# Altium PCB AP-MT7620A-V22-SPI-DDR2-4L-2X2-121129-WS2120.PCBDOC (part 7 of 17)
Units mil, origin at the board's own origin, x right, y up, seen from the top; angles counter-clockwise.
Board outline 7316 x 4279 mil, 4 copper layers (Top, Inner Layer 2, Inner Layer 3, Bottom), stack 35.4 mil thick; 640 components, 473 nets, 2041 pads, 2358 vias.
Unrouted connection lines stored in the file: 11.
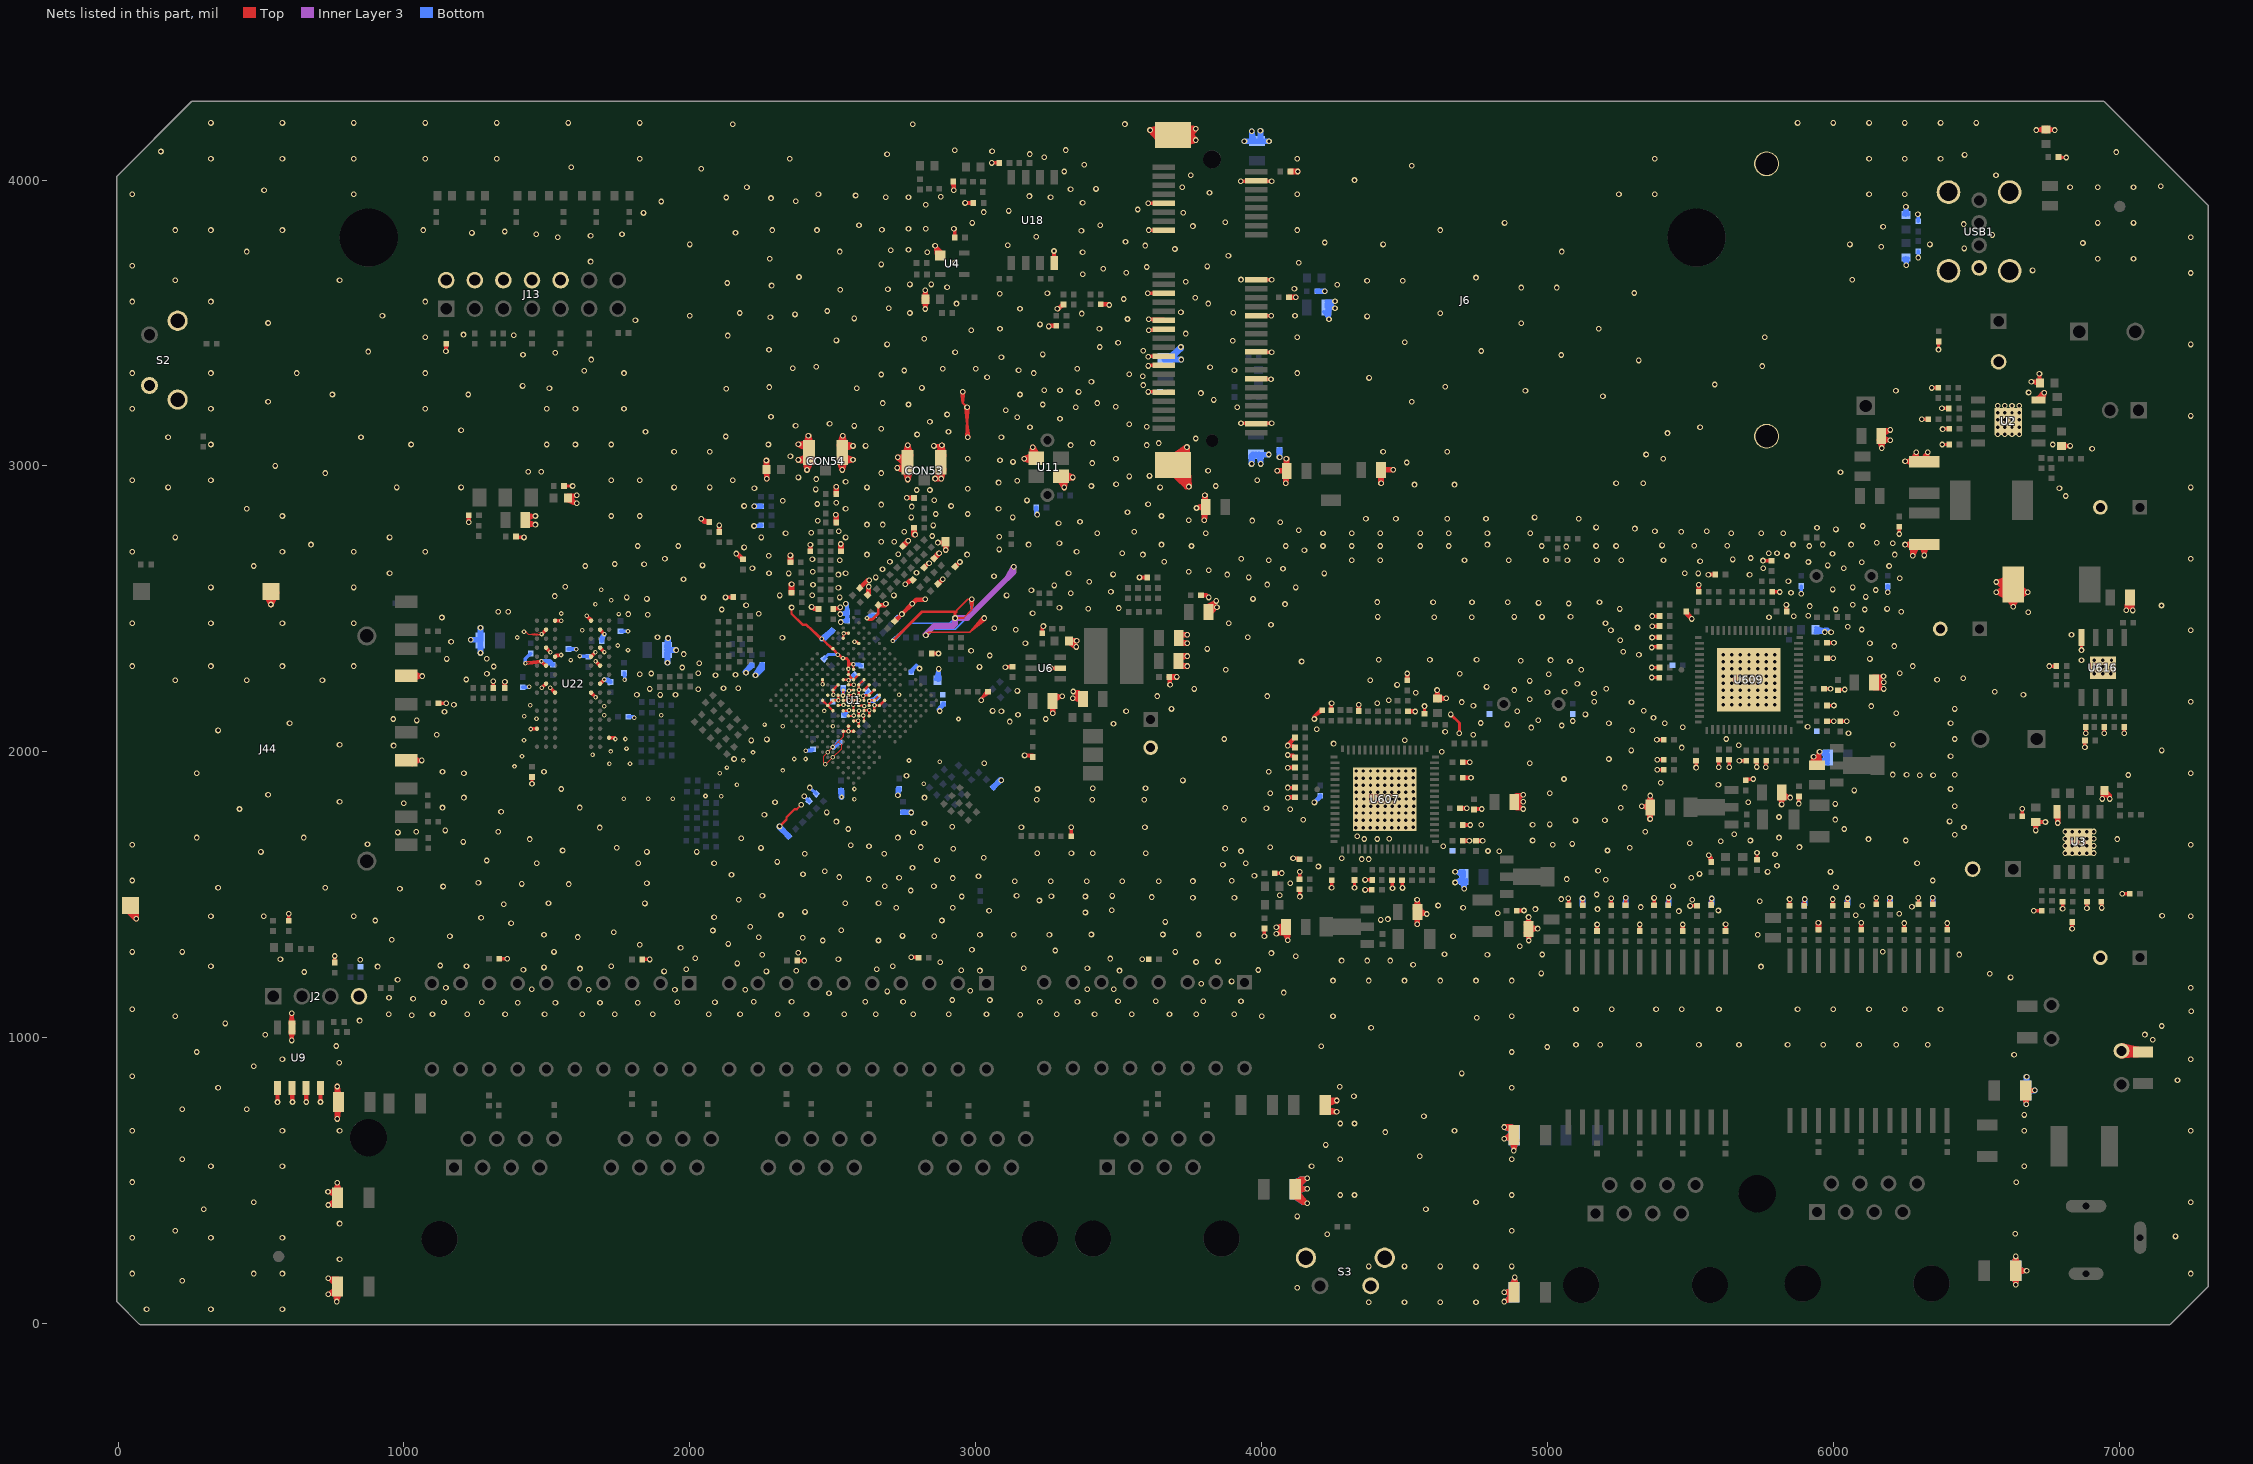
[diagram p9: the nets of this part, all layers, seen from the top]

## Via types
v1: diameter 20, hole 12, Top to Bottom, 2117 vias
v2: diameter 16, hole 8, Top to Bottom, 241 vias

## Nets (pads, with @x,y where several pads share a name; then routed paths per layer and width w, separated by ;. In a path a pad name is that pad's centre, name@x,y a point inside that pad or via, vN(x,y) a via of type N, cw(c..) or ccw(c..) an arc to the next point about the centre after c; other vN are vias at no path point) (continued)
GND: C1.2 C2.2 C5.2 C6.2 C7.2 C8.2 C9.2 C11.2 C12.2 C13.2 C16.2 C17.2 C18.2 C19.2 C21.2 C22.2 C23.2 C24.2 C29.2 C30.2 C32.2 C33.2 C34.2 C36.2 C39.2 C40.2 C41.2 C42.2 C43.2 C44.2 C45.2 C46.2 C47.2 C48.2 C50.2 C51.2 C52.2 C53.2 C54.2 C55.2 C56.2 C57.2 C58.2 C69.1 C70.2 C72.2 C73.2 C75.2 C76.2 C79.1 C82.2 C83.2 C87.2 C88.2 C90.2 C91.2 C93.2 C94.2 C97.2 C99.2 C100.2 C103.2 C104.2 C105.2 C107.2 C108.2 C110.2 C111.2 C112.2 C114.2 C115.2 C116.1 C117.1 C118.1 C119.1 C120.1 C121.2 C122.1 C125.2 C128.2 C129.2 C130.2 C131.2 C132.2 C133.2 C134.2 C135.2 C136.2 C137.2 C138.2 C139.2 C140.2 C166.2 C167.2 C193.2 C195.2 C200.2 C210.2 C215.2 C216.2 C217.2 C218.2 C219.2 C222.2 C223.2 C228.2 C229.2 C230.2 C231.2 C232.2 C275.2 C310.2 C311.2 C312.2 C313.2 C314.2 C315.2 C317.2 C318.2 C366.2 C455.1 C456.2 C457.2 C631.2 C632.2 C633.2 C634.2 C635.2 C636.2 C637.2 C638.2 C639.2 C640.2 C641.2 C642.2 C643.2 C644.2 C645.2 C646.2 C647.2 C648.2 C649.2 C650.2 C651.2 C652.2 C654.2 C655.2 C656.2 C657.2 C658.1 C660.2 C661.2 C662.2 C663.2 C664.2 C665.1 C667.2 C668.2 C669.2 C670.2 C671.2 C673.2 C674.2 C675.2 C676.2 C677.2 C678.2 C680.2 C681.2 C682.2 C683.2 C684.2 C686.2 C687.2 C688.2 C706.2 C707.2 C708.2 C709.2 C710.2 C711.2 C712.2 C713.2 C714.1 C715.1 C716.1 C717.1 C718.2 C719.2 C720.2 C721.2 C722.2 C723.2 C724.2 C725.2 C726.1 C727.1 C728.1 C729.1 C730.1 C731.1 C733.1 C734.1 C768.2 C769.2 C796.2 C797.2 C798.2 C799.2 C801.2 C802.2 C803.2 C804.2 C806.2 C807.2 C808.2 C809.2 C810.1 C811.2 C812.2 C813.2 C814.1 C815.2 C816.1 C817.1 C821.2 C840.2 C841.2 C842.2 C843.2 C844.2 C845.2 C846.2 C847.2 C848.2 C849.2 CON53.2 CON53.3 CON54.2 CON54.3 D3.1 D4.1 D42.1 J2.4 J6.4 J6.9 J6.15 J6.18 J6.21 J6.26 J6.27 J6.29 J6.34 J6.35 J6.37 J6.40 J6.43 J6.50 J6.53 J6.54 J6.57 J6.58 J13.2 J13.4 J13.6 J13.8 J13.10 J44.3 J44.6 J44.GND1 J44.GND2 L6.2 L9.2 L36.2 R5.2 R7.2 R11.2 R12.2 R19.2 R24.2 R42.1 R51.2 R54.2 R107.2 R126.1 R127.1 R130.1 R131.1 R134.1 R135.1 R139.1 R142.1 R159.1 R257.2 R271.2 R274.2 R351.2 R381.2 R467.2 R468.2 R477.1 R560.2 R561.2 R676.2 R678.2 R679.2 R680.2 R682.2 R691.2 R694.2 R698.2 R699.2 R718.2 R721.2 R723.2 R728.2 R743.2 R744.2 R813.2 R825.2 RC1.2 RC2.2 RC3.2 S2.2 S2.3 S2.4 S3.2 S3.3 S3.4 U1.C2 U1.C4 U1.D2 U1.F2 U1.F6 U1.F7 U1.F8 U1.F9 U1.F10 U1.F11 U1.F12 U1.G6 U1.G7 U1.G8 U1.G9 U1.G10 U1.G11 U1.G12 U1.H6 U1.H7 U1.H8 U1.H9 U1.H10 U1.H11 U1.H12 U1.J6 U1.J7 U1.J8 U1.J9 U1.J10 U1.J11 U1.J12 U1.K4 U1.K6 U1.K7 U1.K8 U1.K9 U1.K10 U1.K11 U1.K12 U1.L6 U1.L7 U1.L8 U1.L9 U1.L10 U1.L11 U1.L12 U1.M6 U1.M7 U1.M8 U1.M11 U1.M12 U1.N11 U2.4 U2.9 U3.4 U3.9 U4.1 U6.5 U9.1 U9.2 U9.3 U9.4 U9.7 U11.2 U11.4 U18.4 U22.A3 U22.A7 U22.B2 U22.B8 U22.D2 U22.D8 U22.E3 U22.E7 U22.F2 U22.F8 U22.H2 U22.H8 U22.J3 U22.J7 U22.N1 U22.P9 U607.65 U609.65 U616.4 U616.9 UC1.2 UC2.2 USB1.4 USB1.5 USB1.6 USB1.7 USB1.8 | length 52183.3
  Top w4: v2(1420,2420) 1427,2420 1435,2412 v2(1481.5,2412) ; v2@1424.48,2315.98 1471.14,2317 ; v2@1426.28,2304.14 1471.14,2317 ; v2@1479.31,2322.76 1435.16,2306.68 ; v2@1479.91,2322.9 1435.04,2311.52 ; v2@1480.51,2322.98 1435,2316.21 ; v2@1480.61,2311.01 1435,2317 v2@1480.61,2322.99 ; v2@1480.71,2311.01 1435,2316.21 ; v2@1481.11,2406.01 1435.5,2412 v2@1481.11,2417.99 ; v2@1481.32,2311.01 1435.04,2311.52 ; v2@1481.94,2311.07 1435.16,2306.68 ; U1.N11@2532.93,2071.01 2536.81,2053.31 ; U1.N11@2540.69,2071.01 2536.81,2053.31 ; 1435,2316.21 v2(1481,2317) ; 1435.04,2311.52 v2(1481,2317) ; 1435.16,2306.68 v2(1481,2317) ; 1471.14,2317 v2(1425,2310) 1432,2317 v2(1481,2317) ; 2519.25,2035.75 2536.81,2053.31 ; 2519.25,2035.75 2531,2024 2531,2011.5 v2(2500.5,1981) 2476,1956.5 v2(2473.5,1956.5) 2468,1962 2468,1984.5 v2(2482.5,1999) v2(2500.5,2017) 2519.25,2035.75 ; 2536.81,2053.31 U1.N11@2536.81,2071.43 2536.81,2053.31
  Top w5: v1(2826,2408) 2836,2418 2980,2418 v1(3030,2468) 2983.39,2421.39 ; v1@3024.4,2472.99 2983.39,2421.39 ; v1@3034.99,2462.4 2983.39,2421.39
  Top w6: v1(2928,2468) 2957.46,2468 2986,2496.54 ; 2932,2490 2934,2492 2934,2495.46 2972.54,2534 v1(2986,2534) ; v1@2979.03,2533.35 2986,2496.54 ; v1@2992.97,2533.35 2986,2496.54 ; 2986,2496.54 v1(2986,2534) ; 2986,2496.54 v1(2986,2534)
  Top w8: v1(2314,1739) 2337.95,1762.95 2337.95,1771 2366.5,1799.55 2374.55,1799.55 v1(2390,1815) ; v1(2356,2505) 2356,2483 2394,2445 2407,2445 2456.5,2395.5 v2@2462.5,2395.5 ; 2409.86,2442.14 v2(2462,2396) v2@2462.5,2395.5 ; U1.K4@2464.43,2252.38 v2(2464.5,2236) U1.K4@2464.5,2252.38 ; v2(2536,2197) 2536.81,2197.81 U1.J7@2536.81,2216.19 ; U1.N11@2536.81,2071.43 v2(2555.3,2071.9) ; U1.L9@2536.81,2143.81 2555.81,2143.81 v2(2557,2145) ; U1.N11@2537.28,2071.9 v2(2555.3,2071.9) ; U1.M11@2554.9,2089.52 v2(2555.3,2071.9) ; U1.M11@2555.3,2089.13 v2(2555.3,2071.9) ; v2(2556,2180) v2@2554.9,2178.9 ; v2(2557,2214) v2@2559.19,2216.19 ; v2(2572,2164) v2@2573,2163 ; U1.M12@2572.53,2071.9 v2(2555.3,2071.9) ; U1.M12@2573,2071.43 v2(2555.3,2071.9) ; v2(2574,2127) 2573,2126 v2@2573,2125.71 ; v2(2574,2199) v2@2573.1,2198.1 ; v2(2574,2235) v2@2573.29,2234.29 ; v2(2592,2144) v2@2591.1,2143.1 ; v2(2592,2217) v2@2591.55,2217.45 ; v2(2607,2127) v2@2609.19,2124.81 ; v2(2610,2160) v2@2608.1,2161.9 ; v2(2646,2163) 2645.38,2162.38 v2@2645.38,2161.9 ; v1@2949.02,3259.55 2955,3220 ; v1@2960.98,3259.55 2955,3220 ; v1@2964.01,3204.7 2970,3145 v1@2975.99,3204.7 ; v1@2966,3100.1 2970,3160.02 ; v1@2972,3096 2970,3099 v1(2970,3205) 2955,3220 ; v1(2972,3100) 2970,3160.02 ; v1@2977.98,3100.5 2970,3160.02 ; v1(3020,2180) v1@3020,2187 ; C54.2@3038.38,2213.83 v1@3020,2187 ; C54.2@3043,2210 v1@3020,2187 ; C54.2@3046.83,2205.38 v1@3020,2187 ; v2@2462.5,2395.5 2481.07,2376.93 2481.07,2376.59 ; U1.M6@2464.43,2180 U1.M7@2482.52,2161.9 ; U1.M6@2464.43,2180 U1.M7@2482.52,2161.9 ; U1.M6@2464.43,2180 U1.M7@2482.52,2161.9 ; U1.M6@2464.43,2180 U1.M7@2482.52,2161.9 ; 2481.07,2376.59 2498.66,2359 U1.F2@2500.62,2360.95 ; 2481.07,2376.59 U1.F2@2500.62,2360.95 ; U1.M7@2482.52,2161.9 U1.L7@2500.62,2180 ; U1.M7@2482.52,2161.9 U1.M8@2500.62,2143.81 ; U1.M7@2482.52,2161.9 U1.L7@2500.62,2180 ; U1.M7@2482.52,2161.9 U1.L7@2500.62,2180 ; U1.M7@2482.52,2161.9 U1.M8@2500.62,2143.81 ; U1.M7@2482.52,2161.9 U1.L7@2500.62,2180 ; U1.M7@2482.52,2161.9 U1.M8@2500.62,2143.81 ; U1.M7@2482.52,2161.9 U1.M8@2500.62,2143.81 ; U1.L7@2500.62,2180 v2(2520,2180) ; U1.K6@2500.62,2216.19 2502.4,2214.41 v2(2502.4,2199.7) U1.K6@2500.62,2216.19 ; U1.K6@2500.62,2216.19 U1.J6@2518.71,2234.29 ; U1.K6@2500.62,2216.19 U1.J6@2518.71,2234.29 ; U1.K6@2500.62,2216.19 U1.J6@2518.71,2234.29 ; U1.K6@2500.62,2216.19 U1.J6@2518.71,2234.29 ; U1.F2@2500.62,2360.95 2499.73,2360.06 2518.89,2340.89 U1.F2@2500.62,2360.95 ; v2(2520,2180) 2520,2196.81 U1.K7@2518.71,2198.1 v2(2520,2180) ; v2@2537.65,2414.19 2537.65,2397.14 U1.D2@2536.81,2397.14 v2@2537.65,2414.19 ; v2@2537.65,2414.19 v2(2538.48,2414.19) v2@2538.48,2414.72 ; v2@2538.48,2414.72 2554.9,2414.72 U1.C2@2554.9,2415.24 v2@2538.48,2414.72 ; v2@2553.81,2180 v2@2554.9,2178.9 ; v2@2553.81,2180 U1.K8@2536.81,2180 v2@2553.81,2180 ; v2@2554.02,2252.38 U1.H6@2536.81,2252.38 v2@2554.02,2252.38 ; v2@2554.02,2252.38 v2(2555.5,2250.9) 2564.99,2260.39 ; v2@2554.9,2178.9 U1.K9@2554.9,2161.9 v2@2554.9,2178.9 ; U1.G6@2554.9,2270.48 2554.9,2289.9 U1.G6@2554.9,2270.48 ; U1.G6@2554.9,2270.48 2564.99,2260.39 ; U1.G6@2554.9,2270.48 2564.99,2260.39 ; v2@2559.19,2216.19 U1.H8@2573,2216.19 v2@2559.19,2216.19 ; 2564.99,2260.39 U1.G7@2573,2252.38 ; v2@2573,2125.71 U1.L10@2554.9,2125.71 v2@2573,2125.71 ; v2@2573,2163 U1.K10@2573,2143.81 v2@2573,2163 ; U1.G7@2573,2252.38 U1.F7@2591.1,2270.48 U1.G7@2573,2252.38 ; v2@2573.1,2198.1 U1.J8@2554.9,2198.1 v2@2573.1,2198.1 ; v2@2573.29,2234.29 U1.H7@2554.9,2234.29 v2@2573.29,2234.29 ; 2584.64,2385.5 U1.C4@2591.1,2379.05 ; 2584.64,2385.5 v2(2576.1,2385.5) U1.C4@2591.1,2379.05 ; 2584.64,2385.5 U1.C4@2591.1,2379.05 ; 2584.64,2385.5 U1.C4@2591.1,2379.05 ; v2(2589,2109) v2@2591.1,2106.9 ; v2(2589,2109) 2574.38,2109 U1.L11@2573,2107.62 v2(2589,2109) ; v2@2591.1,2106.9 U1.L12@2591.1,2089.52 v2@2591.1,2106.9 ; v2@2591.1,2143.1 U1.K11@2591.1,2125.71 v2@2591.1,2143.1 ; v2@2591.1,2217 U1.H9@2591.1,2198.1 v2@2591.1,2217 ; v2@2591.1,2217 v2@2591.55,2217.45 ; v2@2591.1,2217.9 U1.G8@2591.1,2234.29 ; v2@2591.1,2217.9 v2@2591.55,2217.45 ; v2@2591.1,2217.9 U1.G8@2591.1,2234.29 ; U1.G8@2591.1,2234.29 U1.F8@2609.19,2252.38 ; U1.G8@2591.1,2234.29 U1.F8@2609.19,2252.38 ; U1.G8@2591.1,2234.29 U1.F8@2609.19,2252.38 ; U1.G8@2591.1,2234.29 U1.F8@2609.19,2252.38 ; v2@2608.1,2161.9 U1.J10@2591.1,2161.9 v2@2608.1,2161.9 ; v2@2609.1,2198.1 U1.G10@2627.29,2198.1 ; v2@2609.1,2198.1 v2(2607,2196) v2@2609.19,2193.81 ; v2@2609.1,2198.1 U1.G10@2627.29,2198.1 ; v2@2609.19,2124.81 U1.K12@2609.19,2107.62 v2@2609.19,2124.81 ; v2@2609.19,2193.81 U1.H10@2609.19,2180 v2@2609.19,2193.81 ; v2@2627.29,2144.29 U1.J12@2627.29,2125.71 v2@2627.29,2144.29 ; v2@2627.29,2144.29 v2(2628,2145) ; v2@2627.29,2177.29 U1.H11@2627.29,2161.9 v2@2627.29,2177.29 ; v2@2627.29,2177.29 v2(2628,2178) 2630,2180 U1.G11@2645.38,2180 ; U1.G10@2627.29,2198.1 U1.F10@2645.38,2216.19 ; U1.G10@2627.29,2198.1 U1.F10@2645.38,2216.19 ; U1.G10@2627.29,2198.1 U1.F10@2645.38,2216.19 ; U1.G10@2627.29,2198.1 U1.F10@2645.38,2216.19 ; v2(2628,2145) 2610.38,2145 U1.J11@2609.19,2143.81 v2(2628,2145) ; v2@2645.38,2161.9 U1.G12@2663.48,2161.9 ; v2@2645.38,2161.9 U1.G12@2662,2161.9 ; v2@2645.38,2161.9 U1.H12@2645.38,2143.81 v2@2645.38,2161.9 ; v2@2645.38,2161.9 U1.G12@2663.48,2161.9 ; v2@2645.38,2161.9 U1.G12@2663.48,2161.9 ; U1.G11@2645.38,2180 U1.F11@2663.48,2198.1 U1.G11@2645.38,2180 ; U1.G12@2662,2161.9 U1.F12@2680.1,2180 ; U1.G12@2662,2161.9 U1.F12@2681.57,2180 ; U1.G12@2663.48,2161.9 U1.F12@2680.1,2180 ; U1.G12@2663.48,2161.9 U1.F12@2681.57,2180 ; U1.F12@2680.1,2180 U1.F12@2681.57,2180 ; 2955,3220 v1(2955,3260) 2955,3220 ; U1.L8@2518.71,2161.9 2520.81,2164 v2(2537.6,2164) U1.L8@2518.71,2161.9 ; U1.J9@2573,2180 2574,2181 v2(2592,2181) U1.J9@2573,2180 ; U1.F6@2573,2288.57 2573,2306 U1.F6@2573,2288.57 ; U1.G9@2609.19,2216.19 U1.F9@2627.29,2234.29 U1.G9@2609.19,2216.19
  Top w10: U1.K4@2464.43,2252.38 U1.K4@2464.5,2252.38 ; v2(2518,2340) 2518.89,2340.89 2519.5,2341.5 2534.5,2326.5 v2(2536,2328) 2536,2326 2549,2326 2555,2320 2555,2307 ; v2@2554.9,2289.9 v2(2555,2290) 2555,2307 ; v2@2573,2306 v2(2572.5,2306.5) 2572,2307 2555,2307 ; v2@2622,2468 v2(2620,2468) 2625,2463 2637.97,2463 2659.39,2484.42 ; v2(2710,2388) 2812,2490 2932,2490 2928,2486 v1(2928,2468) ; v1(4662,2131) 4692,2101 v1(4692,2065) ; C842.2@2659.22,2513.12 2659.39,2493.98 ; C842.2@2659.22,2513.12 2659.39,2493.98 ; C842.2@2659.22,2513.12 2659.39,2484.42 ; 2659.39,2484.42 2659.39,2493.98
  Top w12: U9.7@602.02,1022.68 v1(607.9,990.5) ; U9.7@607.9,1013.8 v1(608.2,1085.8) ; U9.7@608,1023.21 v1(607.9,990.5) ; U9.7@613.98,1022.64 v1(607.9,990.5) ; R54.2@758,1263 v1(758,1286) ; C122.1@760.41,134.28 v1(735,159) ; C122.1@760.99,126.07 v1(735,103) ; C116.1@761.61,436.42 v1(735,415) ; C116.1@762.88,443.01 v1(734.5,461.5) ; C116.1@767.43,469.43 v1(734.5,461.5) ; C122.1@767.88,114.25 v1(735,103) ; C122.1@767.88,145.75 v1(735,159) ; C116.1@767.88,424.25 v1(735,415) ; C116.1@767.88,455.75 v1(734.5,461.5) ; C116.1@768.87,410.6 v1(735,415) ; C122.1@769.68,100.69 v1(735,103) ; C122.1@770.45,159.19 v1(735,159) ; J44.6@1028.96,2250.24 v1@1063.45,2265.55 ; J44.6@1028.96,2280.86 v1@1063.45,2265.55 ; J44.3@1029.4,1955.06 v1@1059,1970.28 ; J44.3@1029.4,1985.49 v1@1059,1970.28 ; C275.2@1121,2170 v1(1148.5,2170) ; C125.2@1313,2223 v1(1313,2247) ; C115.2@1334,1276 v1(1362,1276) ; C45.2@1424.45,2800 v1(1460,2795) ; C45.2@1424.45,2822 v1(1460,2825) ; C45.2@1424.6,2789 v1(1460,2795) ; C45.2@1425.22,2832.97 v1(1460,2825) ; C45.2@1427.05,2811.31 v1(1460,2825) ; C45.2@1427.63,2810.53 v1(1460,2795) ; v2(1444,2080) v2@1444.84,2080.84 ; v2(1550,2458.5) v2@1549.71,2458.79 ; C52.2@1560,2930 v1(1590,2930) ; C53.2@1571.66,2878.56 v1(1604.8,2869.8) ; C53.2@1573.56,2897.93 v1(1605,2898) ; C53.2@1574.59,2890 v1(1605,2898) ; C53.2@1577.59,2882.58 v1(1605,2898) ; C53.2@1579.17,2892.56 v1(1604.8,2869.8) ; U22.B8@1686.04,2427.3 v2(1701.5,2412) ; U22.P9@1717.54,2049.34 1735.66,2049.34 v2(1740,2045) ; C114.2@1834,1274 v1(1860,1274) ; C112.2@2376,1270 v1(2400,1270) ; U1.N11@2536.81,2071.43 U1.N11@2537.28,2071.9 ; U1.M11@2554.9,2089.52 U1.M11@2555.3,2089.13 ; U1.M12@2572.53,2071.9 U1.M12@2573,2071.43 ; RC1.2@2816.46,3580.1 v1(2824,3549) ; RC1.2@2816.47,3585.96 v1(2824,3615) ; RC1.2@2824.41,3581 v1(2824,3549) ; RC1.2@2824.41,3585 v1(2824,3615) ; RC1.2@2832.32,3586.17 v1(2824,3615) ; RC1.2@2832.33,3579.9 v1(2824,3549) ; U4.1@2863.51,3733.45 v1(2858,3770) ; U4.1@2874.5,3736.92 v1(2858,3770) ; U4.1@2875.68,3736.92 2875.68,3749.68 2877,3751 v1(2858,3770) ; U4.1@2883.88,3743.61 v1(2858,3770) ; v1(2924,3830) 2927,3827 C200.2@2927,3799 ; v1(3104,2296) v1@3106,2298 ; C29.2@3233,2415 3233,2436 v1(3237,2440) ; C48.2@3268.45,2178 3268.45,2190.45 3272,2194 v1(3303,2194) ; C48.2@3268.45,2189 v1(3303,2194) ; C48.2@3268.61,2200 v1(3303,2194) ; C48.2@3271.72,2178.5 v1(3303,2194) ; U6.5@3286.34,2293 v1(3263,2293) U6.5@3296.18,2293 ; C79.1@3334,1705 v1(3334,1736) ; C56.2@3369.74,2186.66 v1(3341,2211) ; C56.2@3373.24,2174.24 v1(3340,2187) ; C56.2@3374.47,2195.95 v1(3340,2187) ; C56.2@3375.55,2196 v1(3341,2211) ; C56.2@3378.41,2206.62 v1(3341,2211) ; J6.43@3628.47,3257.6 v1(3604,3259) 3656.6,3259 J6.43@3658,3257.6 ; J6.37@3628.47,3352.09 v1@3606.09,3352.09 ; J6.35@3628.47,3383.58 v1@3605.58,3383.58 ; J6.29@3628.47,3478.07 v1(3605,3475) 3654.93,3475 J6.29@3658,3478.07 ; J6.27@3628.47,3509.57 v1(3605,3513) 3658,3513 J6.27@3658,3509.57 ; J6.21@3628.47,3604.06 v1(3602,3604) 3657.94,3604 J6.21@3658,3604.06 ; J6.15@3628.47,3824.53 v1(3605,3825) 3657.53,3825 J6.15@3658,3824.53 ; J6.9@3628.47,3919.02 v1(3604,3919) J6.9@3658,3919.02 ; C46.2@3807.9,2509.84 v1@3841.86,2528.14 ; C46.2@3814.64,2512 v1(3844,2506) ; C46.2@3818.24,2490.68 v1(3844,2506) ; C46.2@3823.22,2494.37 v1@3841.86,2528.14 ; v1(3842,2528) v1@3841.86,2528.14 ; J6.50@3951.31,3147.36 v1(3928,3149) 3979.19,3149 J6.50@3980.83,3147.36 3982.47,3149 v1(4035,3149) J6.50@4010.36,3147.36 ; J6.4@3951.31,3997.76 v1(3927,3996) J6.4@3985,3996 ; J6.40@3980.83,3304.84 3982.68,3303 v1(4033,3303) J6.40@4010.36,3304.84 ; J6.34@3980.83,3399.33 3982.17,3398 v1(4035,3398) J6.34@4010.36,3399.33 ; J6.26@3980.83,3525.32 3981.15,3525 v1(4034,3525) J6.26@4010.36,3525.32 ; J6.18@3980.83,3651.3 3981.13,3651 v1(4035,3651) J6.18@4010.36,3651.3 ; J6.4@3980.83,3997.76 3982.59,3996 J6.4@3985,3996 ; v1(4010,1355) R468.2@4010,1382 ; J6.4@4010.36,3997.76 v1(4035,3996) J6.4@3985,3996 ; v1(4051.99,1386.05) v1@4053.99,1388.05 ; C631.2@4080.05,1386.58 v1(4051.99,1364.05) ; C631.2@4083.62,1377.22 v1@4053.99,1388.05 ; C631.2@4083.62,1398.88 v1@4053.99,1388.05 ; C631.2@4085.54,1377.05 v1(4051.99,1364.05) ; C631.2@4085.54,1388.05 v1@4053.99,1388.05 ; C631.2@4087.9,1366.31 v1(4051.99,1364.05) ; C631.2@4091.8,1364.05 v1(4051.99,1364.05) ; C117.1@4113.51,498.63 v1(4160,508) ; C117.1@4126.22,474.72 v1(4160,508) ; v1(4185,2115) 4185,2125 ; C642.2@4244,2145 4244,2169 v1(4245,2170) ; v1(4325,1525) C647.2@4325,1552 ; v1(4362,1517) v1@4363,1518 ; R718.2@4570,2133 v1(4570,2160) ; RC2.2@4607.12,2187.96 v1@4615,2210 ; v1(4614,2216) v1@4615,2210 ; RC2.2@4617,2186.59 v1(4646,2187) ; RC2.2@4617.99,2194.53 v1(4646,2187) ; RC2.2@4618.22,2178.68 v1(4646,2187) ; RC2.2@4622.88,2187.96 v1@4615,2210 ; C734.1@4869.39,641.94 v1(4882.6,605.4) ; C733.1@4869.65,129.25 v1(4885.3,161.6) ; C733.1@4874.58,105.13 v1(4849,77) ; C734.1@4875.53,671.54 v1(4848.8,646.4) ; C733.1@4880.12,96.6 v1(4849,110) ; C733.1@4880.12,123.4 v1(4849,110) ; C680.2@4880.35,1845.61 v1(4915,1850) ; C680.2@4880.93,1802.34 v1(4915,1800) ; C733.1@4882.88,94.25 v1(4849,77) ; C733.1@4882.88,125.75 v1(4885.3,161.6) ; C734.1@4882.88,644.25 v1(4882.6,605.4) ; C680.2@4883.44,1813.05 v1(4915,1800) ; C680.2@4883.44,1835.05 v1(4915,1850) ; C734.1@4885.49,646.57 v1(4848.8,646.4) ; C733.1@4886.8,81.14 v1(4849,77) ; C680.2@4889.22,1822.41 v1(4915,1800) ; C680.2@4889.65,1825.97 v1(4915,1850) ; C734.1@4896.34,641.74 v1(4882.6,605.4) ; C733.1@4896.46,127.44 v1(4885.3,161.6) ; C682.2@4922.71,1394.47 v1@4933.44,1417 ; C682.2@4922.74,1367.48 v1(4935,1340) ; C682.2@4933.44,1370.05 v1(4935,1340) ; C682.2@4933.44,1392.05 v1@4933.44,1417 ; C682.2@4944.17,1394.47 v1@4933.44,1417 ; C682.2@4944.34,1368.6 v1(4935,1340) ; v1(5073,1488) 5074,1487 C706.2@5074,1463 ; C637.2@5348.73,1819.06 v1(5359.5,1847) ; C637.2@5356.1,1795.6 v1(5330,1810) ; C637.2@5358.96,1817.03 v1(5330,1810) ; C637.2@5359.54,1804.99 C637.2@5359.54,1806.05 ; C637.2@5359.54,1817.05 v1(5359.5,1847) ; v1(5365,2365) 5368.05,2368.05 C645.2@5391.99,2368.05 ; v1(5366,2400) 5367,2401 R694.2@5391,2401 ; v1(5367,2439) 5368,2440 R698.2@5392,2440 ; v1(5367,2475) R699.2@5392,2475 ; C637.2@5370.35,1819.08 v1(5359.5,1847) ; v1(5373,1489) v1(5373,1489) C710.2@5373.05,1463 ; C711.2@5423.05,1463 5423.05,1488.05 v1(5424,1489) ; v1(5499,1461) v1@5500,1462 ; C713.2@5573,1464 5573,1487 v1(5575,1487) ; C660.2@5694,1900 5694,1905 v1(5720,1905) C660.2@5694,1901 ; R561.2@5733,1623 v1(5733,1647) ; C664.2@5785.99,2560.05 5811.95,2560.05 v1(5813,2559) ; C671.2@5808.6,1844.19 v1(5819,1816) ; C671.2@5819.23,1835.05 v1(5849,1840) ; C671.2@5823.57,1856.24 v1(5849,1840) ; C671.2@5830.22,1843.88 v1(5819,1816) ; C718.2@5847,1462 v1(5847,1485) ; C719.2@5898,1462 5898,1483 v1(5900,1485) ; C687.2@5921.13,1955.13 v1(5931,1983) ; C687.2@5932,1953.45 v1(5931,1983) ; C687.2@5942.73,1955.86 v1(5931,1983) ; C687.2@5943,1953.45 5940.82,1955.62 5938.45,1958 5931,1958 v1(5931,1983) ; C676.2@5967,2221 v1(5990,2221) ; C720.2@5998,1462 v1(5998,1485) ; C681.2@6023.99,2107.05 v1(6046.99,2107.05) ; C721.2@6048,1464 6048,1484.9 v1(6050.1,1487) ; C686.2@6140.39,2263.86 v1@6176,2265 ; C686.2@6140.52,2263.88 v1(6175.5,2264.5) ; C686.2@6140.67,2220.19 v1(6176,2220) ; C686.2@6142.44,2231.05 v1(6176,2220) ; C686.2@6143.93,2252.95 v1(6176,2243) ; C686.2@6144.55,2231.25 v1(6176,2243) ; C686.2@6147.46,2240.84 v1(6176,2220) ; C686.2@6147.63,2243.35 v1(6175.5,2264.5) ; C686.2@6147.68,2243.38 v1@6176,2265 ; C722.2@6150,1467 v1(6150,1490) ; C219.2@6165.91,3126.89 v1(6199,3126) ; C219.2@6167.45,3094 v1(6199,3090) ; C219.2@6167.45,3116 v1(6199,3126) ; C219.2@6167.97,3083.01 v1(6199,3090) ; C219.2@6170.7,3104.51 v1(6199,3090) ; C219.2@6172.47,3106.21 v1(6199,3126) ; C723.2@6198,1466 v1(6198,1490) ; v1(6231,2762) C840.2@6231,2787 ; C311.2@6271.78,3020.08 v1(6290,3048) ; C310.2@6278.2,2725 v1(6251,2725) ; v1(6297,1490) 6298,1489 C724.2@6298,1467 ; C311.2@6298.21,3015.69 v1(6290,3048) ; C310.2@6304.54,2722.41 v1(6318,2687) ; C311.2@6306.31,3022.23 v1(6330,3048) ; C310.2@6331.46,2722.41 v1(6318,2687) ; C311.2@6331.52,3013.03 v1(6330,3048) ; v1(6344,3273) v1@6345,3274 ; C725.2@6348,1467 v1(6348,1490) ; v1(6382,3129) v1@6383,3130 ; C730.1@6398,1378 v1(6398,1401) ; C816.1@6624.72,166.48 v1(6638,136) ; C816.1@6624.7,203.44 v1(6638,235) ; D42.1@6628.94,2585 6629,2584.94 D42.1@6629,2569 ; D42.1@6636.72,2559.62 v1(6629,2508) ; C816.1@6638.12,169.25 v1(6638,136) ; C816.1@6638.12,200.75 v1(6638,235) ; C816.1@6640.59,171.54 v1(6676,185) ; C816.1@6640.59,198.46 v1(6676,185) ; D42.1@6648.38,2556.46 v1(6629,2508) ; C816.1@6651.5,166.39 v1(6638,136) ; C816.1@6651.52,203.53 v1(6638,235) ; D42.1@6659.24,2550.55 v1(6629,2508) ; C731.1@6659.94,795.58 v1(6675,767) ; C17.2@6661,1775 v1(6661,1801) ; C731.1@6673.12,799.25 v1(6675,767) ; C731.1@6676.36,801.7 v1@6702,815 ; C731.1@6676.36,828.3 v1@6702,815 ; C731.1@6686.64,797.14 v1(6675,767) ; C23.2@6700.07,1753.32 v1(6708,1725) ; v1(6705,816) v1@6702,815 ; C23.2@6715.93,1753.32 v1(6708,1725) ; C13.2@6720.53,3284.22 v1(6693,3295) ; C13.2@6721.2,3291.2 C13.2@6717.41,3295 ; C13.2@6722.14,3300 v1(6693,3295) ; C13.2@6722.41,3290 C13.2@6717.41,3295 ; C13.2@6722.41,3292 v1(6693,3295) ; C366.2@6744,4177.59 6741.41,4175 v1(6710,4175) ; C366.2@6746,4177.59 v1(6775,4175) ; C366.2@6746.39,4169.6 v1(6775,4175) ; C366.2@6747.8,4185.39 v1(6775,4175) ; C8.2@6798,3069.41 6798.59,3070 v1(6828,3070) ; C8.2@6800,3069.41 v1(6828,3070) ; C8.2@6800.98,3077.35 v1(6828,3070) ; C8.2@6801.31,3061.52 v1(6828,3070) ; U616.4@6868,2379.84 v1(6868,2356) U616.4@6868,2399.33 ; C18.2@6940.67,1864.13 v1(6940.6,1835.2) ; C18.2@6948.59,1863 v1(6940.6,1835.2) ; C18.2@6948.59,1865 6940.6,1864.59 v1(6940.6,1835.2) ; C18.2@6955.9,1859.75 v1(6940.6,1835.2) ; L36.2@7005.53,932.7 R257.2@7064.62,936.69 ; L36.2@7005.95,944.78 R257.2@7064.62,936.69 ; L36.2@7007.2,963.52 R257.2@7066.54,963.78 ; L36.2@7008.13,944.56 R257.2@7067.25,950.12 ; L36.2@7008.38,975.55 R257.2@7066.54,963.78 ; L36.2@7008.71,944.58 R257.2@7071.5,954.06 ; L36.2@7008.71,963.53 R257.2@7071.5,954.06 ; L36.2@7009.39,963.45 R257.2@7067.25,950.12 ; L36.2@7010.3,944.84 R257.2@7066.54,963.78 ; L36.2@7010.48,932.7 R257.2@7067.25,950.12 ; L36.2@7011.51,962.88 R257.2@7064.62,936.69 ; L36.2@7011.64,932.87 R257.2@7071.5,954.06 ; L36.2@7011.64,975.24 R257.2@7071.5,954.06 ; L36.2@7013.29,974.9 R257.2@7067.25,950.12 ; L36.2@7015.31,933.84 R257.2@7066.54,963.78 ; L36.2@7017.93,973.12 R257.2@7064.62,936.69 ; C314.2@7026.7,2531.35 v1(7024.4,2495) ; C314.2@7027.43,2524.46 v1(7047,2494.6) ; C314.2@7037.45,2540 7036,2538.55 C314.2@7036,2535.8 ; C314.2@7047.01,2523.55 v1(7024.4,2495) ; C314.2@7048.37,2530.27 v1(7047,2494.6) ; R257.2@7083,950.12 7079.06,954.06 L36.2@7008,954.06 ; v1(607.9,990.5) v1@607.9,1085.5 ; v1@607.9,1085.5 v1(608.2,1085.8) ; v1@607.9,1085.5 602.01,1048.28 v1(608.2,1085.8) ; v1@607.9,1085.5 613.99,1048.31 v1(608.2,1085.8) ; v1@607.9,1085.5 608,1047.82 v1(608.2,1085.8) ; v1(734.5,461.5) 759.5,461.5 767.88,453.12 C116.1@767.88,440 760,440 757.5,437.5 757.5,415 v1(735,415) ; v1(735,103) 761,103 761,123.12 C122.1@767.88,130 767.88,137 767.88,145.12 754,159 v1(735,159) ; v1@1059,1970.28 v1(1062.5,1970) ; v1@1059,1970.28 J44.3@1008,1970.28 v1(1062.5,1970) ; v1@1059,1970.28 1025.72,1970.28 v1(1062.5,1970) ; v1@1063.45,2265.55 v1(1064,2265) ; v1@1063.45,2265.55 J44.6@1008,2265.55 v1(1064,2265) ; v1@1063.45,2265.55 1025.72,2265.55 v1(1064,2265) ; v2@1444.84,2080.84 U22.N1@1465.57,2080.84 v2@1444.84,2080.84 ; v1(1460,2795) 1424.45,2795 C45.2@1424.45,2811 1438.45,2825 v1(1460,2825) ; v2@1549.71,2458.79 U22.A3@1528.56,2458.79 v2@1549.71,2458.79 ; C53.2@1574.59,2886 v1(1604.8,2869.8) ; C53.2@1574.59,2886 1592.79,2869.8 ; C53.2@1574.59,2886 1592.79,2869.8 ; 1592.79,2869.8 C53.2@1574.59,2888 1577.59,2898 v1(1605,2898) ; 1592.79,2869.8 v1(1604.8,2869.8) ; 1592.79,2869.8 1580.82,2891.02 1592.79,2869.8 ; 1592.79,2869.8 1570.32,2879.23 1592.79,2869.8 ; 2435,2498 v1(2426,2507) C844.2@2450,2500 ; 2435,2498 2448,2498 C844.2@2450,2500 ; 2435,2498 C844.2@2450,2500 ; 2435,2498 C844.2@2450,2500 ; v1(2824,3549) 2824,3582.59 RC1.2@2824.41,3583 2824,3583.41 v1(2824,3615) ; v1@3106,2298 C51.2@3129,2298 v1@3106,2298 ; v1(3340,2187) C56.2@3375.55,2187 ; v1(3340,2187) C56.2@3375.55,2185 C56.2@3375.55,2187 ; v1(3341,2211) 3361,2211 3375.55,2195.45 C56.2@3375.55,2187 ; v1@3605.58,3383.58 J6.35@3658,3383.58 v1(3604,3382) v1@3605.58,3383.58 ; v1@3606.09,3352.09 J6.37@3658,3352.09 v1(3604,3350) v1@3606.09,3352.09 ; v1@3841.86,2528.14 3814.45,2500.72 C46.2@3814.45,2490 3815,2490.55 3828.55,2490.55 v1(3844,2506) ; v1@3841.86,2528.14 3814.45,2501 v1(3844,2506) ; C117.1@4118.12,470 C117.1@4128.3,470 ; C117.1@4118.12,470 4118.12,490.42 4135.7,508 ; C117.1@4118.12,470 v1@4157,470 ; C117.1@4118.12,470 v1(4160,471.6) ; C117.1@4118.12,485.75 4135.7,508 ; C117.1@4118.12,485.75 v1(4160,508) ; C117.1@4118.12,485.75 4135.7,508 ; C117.1@4128.3,470 v1@4157,470 ; C117.1@4128.3,470 4128.3,436.7 4144,421 ; 4135.7,508 v1(4160,508) ; 4135.7,508 4109.74,496.57 4135.7,508 ; 4135.7,508 4130.59,480.11 4135.7,508 ; 4144,421 v1(4160,421) ; 4144,421 4130.14,460.79 v1(4160,421) ; 4144,421 4108.83,444.2 v1(4160,421) ; 4144,421 4118.12,454.25 v1(4160,421) ; v1@4157,470 v1(4160,471.6) ; v1@4157,470 4120.53,483.47 v1(4160,471.6) ; v1@4157,470 4120.53,456.53 v1(4160,471.6) ; 4185,2125 4205,2145 C641.2@4212,2145 4185,2125 ; v1@4363,1518 C654.2@4385,1518 v1@4363,1518 ; v1@4615,2210 RC2.2@4615,2186.59 4615.41,2187 v1(4646,2187) ; v1(4848.8,646.4) 4875.3,646.4 4875.3,652.42 C734.1@4878.94,656.06 ; v1(4848.8,646.4) C734.1@4882.88,660 C734.1@4878.94,656.06 ; v1(4849,77) 4882,110 C733.1@4882.88,110 ; v1(4849,110) C733.1@4884,110 ; v1(4849,110) C733.1@4882.88,110 ; C734.1@4878.94,656.06 4882.6,652.39 v1(4882.6,605.4) ; C733.1@4882.88,110 C733.1@4884,110 ; C680.2@4883.44,1824.05 4883.44,1843.44 4890,1850 v1(4915,1850) ; C680.2@4883.44,1824.05 4884.39,1825 v1(4915,1825) ; C680.2@4883.44,1824.05 v1(4915,1825) ; C680.2@4883.44,1824.05 v1(4915,1825) ; C733.1@4884,110 4884,116.3 4885.3,117.6 v1(4885.3,161.6) ; v1(4915,1800) 4890,1800 4890,1825 v1(4915,1825) ; v1(4915,1825) 4885.03,1834.93 v1(4915,1825) ; v1(4915,1825) 4885.68,1813.28 v1(4915,1825) ; C682.2@4933.44,1381.05 v1@4933.44,1417 ; C682.2@4933.44,1381.05 4935,1379.49 v1(4935,1340) ; C682.2@4933.44,1381.05 v1(4934,1422) v1@4933.44,1417 ; v1(5330,1810) C637.2@5359.5,1810 ; v1(5330,1810) C637.2@5359.54,1806.05 ; C637.2@5359.5,1810 v1(5359.5,1847) ; C637.2@5359.5,1810 5359.5,1806.09 C637.2@5359.54,1806.05 ; C637.2@5359.5,1810 v1(5359.5,1847) ; v1@5500,1462 C712.2@5523,1462 v1@5500,1462 ; R560.2@5573,1615 5573,1629 ; R560.2@5573,1615 5573,1629 ; R560.2@5573,1615 v1(5564,1638) 5573,1629 ; v1(5819,1816) C671.2@5819.44,1857.05 5821.5,1854.99 5821.5,1840 v1(5849,1840) ; v1(5819,1816) 5819.44,1846.05 v1(5849,1840) ; C686.2@6138.98,2263.49 6159.53,2264.5 ; C686.2@6138.98,2263.49 6159.53,2264.5 ; C686.2@6138.98,2263.49 v1(6175.5,2264.5) ; C686.2@6138.98,2263.49 v1(6175.5,2264.5) ; C686.2@6142.44,2253.05 v1(6175.5,2264.5) ; C686.2@6142.44,2253.05 6159.53,2264.5 ; C686.2@6142.44,2253.05 v1@6176,2265 ; C686.2@6142.44,2253.05 6159.53,2264.5 ; C686.2@6143.39,2243 6142.69,2242.31 6142.69,2247.67 6159.53,2264.5 ; C686.2@6143.39,2243 v1(6176,2243) ; C686.2@6143.39,2243 6150,2243 6150,2220 v1(6176,2220) ; 6159.53,2264.5 v1(6175.5,2264.5) ; 6159.53,2264.5 6150.78,2245.88 6159.53,2264.5 ; v1(6175.5,2264.5) v1@6176,2265 ; v1(6176,2243) C686.2@6142.44,2242.05 6145.39,2245 6149,2245 6149,2265 v1@6176,2265 ; v1(6199,3090) 6174,3090 6165,3099 6165,3102.55 C219.2@6167.45,3105 6167.45,3118.45 6177,3126 v1(6199,3126) ; v1(6251,2725) 6317.88,2725 C310.2@6318,2724.88 v1(6318,2687) ; v1(6251,2725) 6281.7,2711.49 v1(6251,2725) ; v1(6251,2725) 6281.79,2738.29 v1(6251,2725) ; v1(6251,2725) 6284.54,2724.88 v1(6251,2725) ; v1(6251,3016) v1@6253,3015.12 ; v1(6251,3016) C311.2@6290,3015.12 ; v1(6251,3016) C311.2@6318,3015.12 ; v1@6253,3015.12 C311.2@6318,3015.12 ; v1@6253,3015.12 C311.2@6290,3015.12 ; v1@6253,3015.12 6281.57,3001.76 v1@6253,3015.12 ; v1@6253,3015.12 6281.57,3028.48 v1@6253,3015.12 ; v1@6253,3015.12 C311.2@6284.54,3015.12 ; v1@6253,3015.12 C311.2@6284.54,3015.12 ; C311.2@6284.54,3015.12 v1(6290,3048) ; C311.2@6290,3015.12 v1(6290,3048) ; C311.2@6318,3015.12 6330,3015.12 v1(6330,3048) ; C311.2@6318,3015.12 v1(6330,3048) ; v1@6345,3274 R5.2@6367,3274 v1@6345,3274 ; v1@6383,3130 C12.2@6405,3130 v1@6383,3130 ; D42.1@6628.94,2560.2 v1(6680,2558) ; D42.1@6628.94,2560.2 v1(6629,2508) ; D42.1@6628.94,2560.2 v1(6629,2508) ; D42.1@6628.94,2560.2 v1(6680,2558) ; v1(6629,2508) 6629,2558.4 D42.1@6629,2569 ; v1(6629,2508) 6598.67,2550.48 v1(6629,2508) ; v1(6629,2508) 6609.51,2556.42 v1(6629,2508) ; v1(6629,2508) 6621.17,2559.61 v1(6629,2508) ; D42.1@6629,2569 6639,2559 D42.1@6639,2558 ; v1(6638,136) C816.1@6638,184.88 ; C816.1@6638,184.88 C816.1@6638.12,185 ; C816.1@6638,184.88 v1(6638,235) ; C816.1@6638.12,185 v1(6676,185) ; C816.1@6638.12,185 v1(6676,185) ; D42.1@6639,2558 v1(6680,2558) ; D42.1@6639,2558 v1(6680,2558) ; v1(6675,767) 6675,813.12 C731.1@6673.12,815 v1@6702,815 ; v1(6680,2558) 6640.13,2589.96 v1(6680,2558) ; v1(6680,2558) 6637.53,2529.58 v1(6680,2558) ; v1(6680,2558) 6633.61,2579.43 v1(6680,2558) ; v1(6680,2558) 6631.94,2540.63 v1(6680,2558) ; v1(6680,2558) 6629.87,2567.94 v1(6680,2558) ; v1(6680,2558) 6629.2,2552.41 v1(6680,2558) ; v1(6693,3295) C13.2@6717.41,3295 ; v1(6708,1725) 6708,1753.6 C23.2@6708,1754.41 v1(6708,1725) ; v1(6710,4175) v1(6775,4175) ; v1(6710,4175) 6741.65,4169.6 v1(6710,4175) ; v1(6710,4175) 6740.37,4185.42 v1(6710,4175) ; v1(6710,4175) 6742,4177.59 v1(6710,4175) ; L36.2@7008,954.06 R257.2@7064.62,936.69 ; L36.2@7008,954.06 R257.2@7066.54,963.78 ; L36.2@7008,954.06 R257.2@7067.25,950.12 ; L36.2@7011.5,954.06 R257.2@7064.62,936.69 ; L36.2@7011.5,954.06 R257.2@7066.54,963.78 ; L36.2@7011.5,954.06 R257.2@7067.25,950.12 ; v1(7024.4,2495) 7024.4,2514.8 7036,2526.4 C314.2@7036,2535.8 ; v1(7024.4,2495) 7037.45,2529 v1(7047,2494.6) ; C314.2@7036,2535.8 7047,2524.8 v1(7047,2494.6) ; R159.1@596.8,1409.2 v1(596.8,1434) R159.1@597,1409 R159.1@596.8,1409.2 ; C47.2@1392,2753 1395,2750 v1(1420,2750) C47.2@1392,2753 ; v1(1448,1888.5) C134.2@1448,1912 v1(1448,1888.5) ; v2(1481,2317) 1496.69,2301.31 U22.F2@1497.07,2301.31 v2(1481,2317) ; v2(1481.5,2412) 1496.8,2427.3 U22.B2@1497.07,2427.3 v2(1481.5,2412) ; v2(1482.5,2224) 1496.82,2238.32 U22.H2@1497.07,2238.32 v2(1482.5,2224) ; U22.D2@1497.07,2363.93 U22.D2@1497.07,2364.3 v2(1512.5,2348.5) U22.D2@1497.07,2363.93 ; v2(1511.5,2224) 1528.56,2206.94 U22.J3@1528.56,2206.82 v2(1511.5,2224) ; U22.E3@1528.56,2332.81 1534.56,2338.8 v2(1549.8,2338.8) U22.E3@1528.56,2332.81 ; v2(1640,2476) 1654.55,2461.45 U22.A7@1654.55,2458.79 v2(1640,2476) ; U22.J7@1654.55,2206.82 1654.68,2206.82 v2(1670.5,2191) U22.J7@1654.55,2206.82 ; U22.E7@1654.55,2332.81 1654.55,2333.05 v2(1670,2348.5) U22.E7@1654.55,2332.81 ; v2(1670.5,2316.5) 1685.69,2301.31 U22.F8@1686.04,2301.31 v2(1670.5,2316.5) ; U22.H8@1686.04,2238.32 1686.04,2238.54 v2(1700.5,2253) U22.H8@1686.04,2238.32 ; U22.D8@1686.04,2364.3 1686.2,2364.3 v2(1701.5,2349) U22.D8@1686.04,2364.3 ; v1(2125,2540) 2150,2540 C846.2@2152,2542 v1(2125,2540) ; v1(2754,2586) 2768,2600 2778.54,2600 C82.2@2780.27,2601.73 v1(2754,2586) ; v1(2775,1281.5) 2798.5,1281.5 C111.2@2800,1280 v1(2775,1281.5) ; v1(3056,4060) C137.2@3082,4060 v1(3056,4060) ; v1(3171,1987.5) 3199,1987.5 C50.2@3200,1982 v1(3171,1987.5) ; R467.2@4046,1575 4047,1576 v1(4071,1576) R467.2@4046,1575 ; v1(4092,1875) R676.2@4117,1875 v1(4092,1875) ; v1(4092,1989) 4109,1989 4117,1981 R678.2@4117,1980 v1(4092,1989) ; v1(4092,2022) 4111,2022 4117,2016 R679.2@4117,2015 v1(4092,2022) ; v1(4110.3,1628.1) 4128.94,1628.1 C634.2@4132.99,1624.05 v1(4110.3,1628.1) ; C632.2@4132.99,1519.05 4134.3,1517.74 v1(4134.3,1493.8) C632.2@4132.99,1519.05 ; C633.2@4132.99,1554.05 4133.2,1554.26 v1(4133.2,1580.1) C633.2@4132.99,1554.05 ; v1(4245,1525) 4245,1550.06 C640.2@4245.99,1551.05 v1(4245,1525) ; v1(4362,1552) R691.2@4387,1552 v1(4362,1552) ; C655.2@4455.99,1551.05 4458,1549.04 v1(4458,1523) C655.2@4455.99,1551.05 ; C656.2@4490.99,1551.05 4493,1549.04 v1(4493,1524) C656.2@4490.99,1551.05 ; C707.2@5123.05,1463 C707.2@5123.05,1463 v1(5123,1487) C707.2@5123.05,1463 ; C708.2@5223.05,1463 C708.2@5223.05,1463 v1(5223,1488) C708.2@5223.05,1463 ; C709.2@5273.05,1463 5274,1463.95 v1(5274,1490) C709.2@5273.05,1463 ; C715.1@5323,1373.06 v1(5323,1396) C715.1@5323.05,1373.01 C715.1@5323,1373.06 ; v1(5365,2260) 5390.04,2260 C644.2@5390.99,2259.05 v1(5365,2260) ; v1(5365,2295) R682.2@5392,2295 v1(5365,2295) ; v1(5383,2042) 5406.94,2042 C643.2@5406.99,2042.05 v1(5383,2042) ; v1(5384,1937) 5406.94,1937 C638.2@5406.99,1937.05 v1(5384,1937) ; v1(5384,1972) 5406.94,1972 C639.2@5406.99,1972.05 v1(5384,1972) ; v1(5520,1945) C646.2@5519.99,1969.05 v1(5520,1945) ; v1(5599,1946) 5599,1971 C651.2@5600,1972 v1(5599,1946) ; C717.1@5623,1373.06 C717.1@5623.05,1373.01 v1(5623,1396.5) C717.1@5623,1373.06 ; R721.2@5635,1972 5636,1971 v1(5636,1946) R721.2@5635,1972 ; v1(5671.5,1969) 5694.94,1969 R728.2@5694.99,1969.05 v1(5671.5,1969) ; C662.2@5729.99,1969.05 5732,1967.04 v1(5732,1947) C662.2@5729.99,1969.05 ; v1(5754,2669) 5782.94,2669 C665.1@5783.59,2668.35 v1(5754,2669) ; v1(5763.5,1946) 5763.5,1967.56 C663.2@5764.99,1969.05 v1(5763.5,1946) ; R743.2@5836,2490 v1(5836,2514) R743.2@5837,2491 R743.2@5836,2490 ; v1(5879,1819) 5879,1843 C688.2@5880,1844 v1(5879,1819) ; R744.2@5977.99,2107.05 R744.2@5977.99,2107.05 v1(6001,2107) R744.2@5977.99,2107.05 ; C675.2@5977.99,2162.05 C675.2@5977.99,2162.05 v1(6002,2162) C675.2@5977.99,2162.05 ; C677.2@5977.99,2327.05 C677.2@5977.99,2327.05 v1(6000,2327) C677.2@5977.99,2327.05 ; C678.2@5977.99,2382.05 C678.2@5977.99,2382.05 v1(6002,2382) C678.2@5977.99,2382.05 ; C684.2@6016,2215 6019,2218 v1(6040,2218) C684.2@6016,2215 ; C728.1@6248,1378.06 C728.1@6248.05,1378.01 v1(6248,1401) C728.1@6248,1378.06 ; v1(6309,3163) R7.2@6332,3163 v1(6309,3163) ; v1(6368,3407) 6368,3434 C6.2@6369,3435 v1(6368,3407) ; v1(6380,3202) 6403,3202 C11.2@6404,3201 v1(6380,3202) ; v1(6381,3075) C9.2@6405,3075 v1(6381,3075) ; v1(6701,1444) R11.2@6729,1444 v1(6701,1444) ; v1(6755,2300) R271.2@6780,2300 v1(6755,2300) ; C24.2@6788,4081 6790,4079 v1(6815,4079) C24.2@6788,4081 ; v1(6802,1451) C21.2@6802,1476 v1(6802,1451) ; v1(6880,2016) R274.2@6880,2040 v1(6880,2016) ; v1(6883,2065) C318.2@6883,2087 v1(6883,2065) ; v1(6887,1453) C22.2@6887,1476 v1(6887,1453) ; C19.2@6937,1476 6939,1474 v1(6939,1454) C19.2@6937,1476 ; v1(6948,2065) C317.2@6948,2087 v1(6948,2065) ; v1(7011,1504) C2.2@7037,1504 v1(7011,1504) ; v1(7018,2065) C315.2@7018,2087 v1(7018,2065)
  Top w15: U9.2@608,812.18 v1(610.4,775.1) 610.4,822.09 U9.2@608,824.49 ; C122.1@755.74,113.19 v1(765,77.2) ; C116.1@755.94,458.15 v1@767.88,486.6 ; C122.1@767.88,114.25 v1(765,77.2) ; C122.1@767.88,137 765,134.12 v1(765,77.2) ; C122.1@779.71,111.33 v1(765,77.2) ; C116.1@779.83,458.15 v1@767.88,486.6 ; R351.2@1353,2223 1353,2245 v1(1353.5,2245.5) ; R134.1@2103,2769 v1(2103,2792) ; v1(2163,2693.5) v1@2164.19,2694.69 ; v1(2526,2506) v1@2526,2501.5 ; C110.2@2594.73,2572.73 2622,2600 v1(2628,2600) ; C842.2@2659.22,2513.12 2683.97,2513.12 2687.43,2516.57 v1(2686,2518) ; C104.2@2716.73,2456.73 v1(2742,2482) ; v1(2778,2518) v1(2742,2482) ; C90.2@2819.73,2644.27 2835.46,2660 v1(2837,2660) ; v1(2824,2534) 2824,2532 2792,2532 v1(2742,2482) ; R381.2@2846,2344 v1(2870,2344) ; v1(2854,3070) 2871.88,3070 v1@2878.07,3063.81 ; CON53.3@2865.27,3038.72 v1@2878.07,3063.81 ; CON53.3@2890.88,3038.72 v1@2878.07,3063.81 ; C456.2@2894.41,2733 v1(2868,2732) 2894.41,2732 C456.2@2894.41,2735 ; v1(3256,3488) 3258,3490 R126.1@3282,3490 ; U18.4@3275,3710.2 3274,3710.2 v1(3274,3752) U18.4@3275,3721.42 ; v1(3286,3550) v1@3288.04,3547.96 ; R127.1@3438,3566 3464,3566 v1(3467,3563) ; C55.2@3677,2262 v1(3680,2234.4) C55.2@3680,2262 ; v1(3772.4,2853) v1@3775.4,2856 ; C32.2@3788,2548 3807,2548 v1(3815,2540) ; C218.2@3803,2846.63 v1@3775.4,2856 ; C218.2@3803,2865.37 v1@3775.4,2856 ; C631.2@4076.47,1374.24 v1(4091.8,1340.8) ; C631.2@4085.54,1377.05 v1(4091.8,1340.8) ; C631.2@4085.54,1388.05 4091.8,1381.79 4091.8,1364.05 v1(4091.8,1340.8) ; v1(4092,1839) v1@4094.05,1841.05 ; v1(4092,1944) v1@4093,1945 ; v1(4092,2022) v1@4092,2025 ; C631.2@4095.03,1377.44 v1(4091.8,1340.8) ; C648.2@4340,2143 v1(4340,2165) ; C658.1@4509.59,2250.35 4509.59,2273.59 v1(4510,2274) ; C657.2@4511.99,2142.05 4536.95,2142.05 v1(4538,2141) ; C661.2@4536.03,1451.37 v1@4545,1481.2 ; C661.2@4545.01,1429.56 v1(4578.2,1432.8) ; C661.2@4545,1432.8 v1(4578.2,1432.8) ; C661.2@4545.44,1439.05 v1(4578.2,1432.8) ; C661.2@4545.44,1450.05 v1@4545,1481.2 ; C661.2@4548.53,1448.03 v1(4578.2,1432.8) ; C661.2@4554.81,1451.63 v1@4545,1481.2 ; C668.2@4694,1803 v1(4718,1803) ; C667.2@4703.99,1744.05 v1(4730,1744) v1(4730,1744) ; C673.2@4749.99,1689.05 v1(4772.99,1689.05) ; C682.2@4934.63,1390.48 v1(4965.4,1381.8) ; C682.2@4935.07,1371.69 v1(4965.4,1381.8) ; C716.1@5473.05,1373.01 5473.05,1395.55 v1(5473.5,1396) ; v1(5563,2619) 5564,2620 C652.2@5587,2620 ; C687.2@5940.82,1955.62 5951.78,1955.62 C687.2@5952,1955.4 ; C687.2@5952.46,1952.59 v1(5952,2000) ; C219.2@6158.16,3091.99 v1(6169.4,3062.6) ; C219.2@6167.45,3094 v1(6169.4,3062.6) ; C219.2@6167.45,3105 6169.4,3103.05 v1(6169.4,3062.6) ; C219.2@6176.91,3093.15 v1(6169.4,3062.6) ; C310.2@6272.35,2724.96 v1(6278.2,2686) ; C310.2@6278.2,2725 v1(6278.2,2686) ; C310.2@6284.54,2724.88 v1(6278.2,2686) ; C310.2@6296.11,2721.09 v1(6278.2,2686) ; D42.1@6616.83,2557.23 v1(6570,2594.2) ; D42.1@6620.27,2589.23 v1(6570,2558.4) ; D42.1@6622.06,2530.69 v1(6570,2558.4) ; D42.1@6624.67,2570.31 v1(6570,2594.2) ; D42.1@6625.86,2615.14 v1(6570,2594.2) ; D42.1@6626.5,2575.3 v1(6570,2558.4) ; D42.1@6627.42,2544.98 v1(6570,2558.4) ; D42.1@6628.94,2560.2 v1(6570,2558.4) ; D42.1@6629,2558.4 v1(6570,2558.4) ; D42.1@6629.35,2600.29 v1(6570,2594.2) ; C23.2@6708,1753.6 6709,1754.6 v1(6741.8,1754.6) C23.2@6710,1754.41 ; v1(6721,3322.8) v1@6721.2,3322.6 ; C13.2@6721.2,3291.2 v1@6721.2,3322.6 ; C13.2@6722.41,3292 v1@6721.2,3322.6 ; C18.2@6948.59,1865 6949.2,1865 6967,1847.2 ; v1(557.8,774.9) v1@558,775.1 ; v1(557.8,774.9) 558,812.18 v1@558,775.1 ; v1(557.8,774.9) U9.1@558,824.49 v1@558,775.1 ; v1@658,775.4 U9.3@658,824.49 v1(658.3,775.1) ; v1@658,775.4 v1(658.3,775.1) ; v1@658,775.4 658,812.18 v1(658.3,775.1) ; v1@708,775.3 U9.4@708,824.49 v1(708.2,775.1) ; v1@708,775.3 v1(708.2,775.1) ; v1@708,775.3 708,812.18 v1(708.2,775.1) ; v1(766.8,493) v1@767.88,486.6 ; v1(766.8,493) C116.1@767.88,440 v1@767.88,486.6 ; v1(766.8,493) 767.88,455.75 v1@767.88,486.6 ; 2051,2804 C847.2@2068,2804 ; 2051,2804 v1(2040,2815) C847.2@2068,2804 ; 2051,2804 C847.2@2068,2804 ; 2051,2804 C847.2@2068,2804 ; v1@2164.19,2694.69 2185.44,2673.44 2185.44,2674 C845.2@2186,2674 v1@2164.19,2694.69 ; v1@2526,2501.5 2502,2501.5 C843.2@2502,2500 v1@2526,2501.5 ; v1@2878.07,3063.81 CON53.3@2878.07,3013 v1(2882,3072) 2878.07,3035.64 v1@2878.07,3063.81 ; v1@3288.04,3547.96 3306.04,3565.96 3307,3565.96 R135.1@3307,3565 v1@3288.04,3547.96 ; v1@3775.4,2856 C218.2@3804.55,2856 v1@3775.4,2856 ; v1@4092,2025 R680.2@4117,2050 v1@4092,2025 ; v1@4093,1945 C636.2@4117,1945 v1@4093,1945 ; v1@4094.05,1841.05 C635.2@4116.99,1841.05 v1@4094.05,1841.05 ; v1@4545,1481.2 v1(4544,1483) 4545,1438.61 v1@4545,1481.2 ; v1(4965.4,1381.8) 4934.19,1381.8 C682.2@4933.44,1381.05 v1(4965.4,1381.8) ; C687.2@5952,1955.4 v1(5952,2000) ; C687.2@5952,1955.4 v1(5952,2000) ; v1(5952,2000) 5933.9,1956.18 v1(5952,2000) ; v1(5952,2000) C687.2@5943,1953.45 v1(5952,2000) ; v1(6570,2594.2) 6619.74,2594.2 D42.1@6628.94,2585 v1(6570,2594.2) ; C18.2@6948.59,1863 6967,1847.2 ; C18.2@6948.59,1863 v1(6967,1835.2) 6967,1847.2 ; C18.2@6948.59,1863 6967,1847.2 ; v1(1147,3401) 1147,3426 R477.1@1148,3427 v1(1147,3401) ; v1(1227,2803) R19.2@1227,2828 v1(1227,2803) ; C105.2@2421,2702 2422,2702 v1(2422,2724) C105.2@2421,2702 ; C841.2@2622.04,2548.48 2626,2552.43 v1(2626,2578) C841.2@2622.04,2548.48 ; v1(2759,2889) 2784,2889 C88.2@2784,2888 v1(2759,2889) ; C83.2@2867.73,2587.73 2868.23,2587.23 v1(2885,2604) C83.2@2867.73,2587.73 ; R825.2@2922,3995 2923,3994 v1(2923,3964) R825.2@2922,3995 ; R107.2@2927.75,2647.71 2928.2,2647.26 v1(2945,2664) R107.2@2927.75,2647.71 ; v1(2963,3920) R142.1@2992,3920 v1(2963,3920) ; v1(3573,2610) R24.2@3600,2610 v1(3573,2610) ; R723.2@4703.99,1689.05 R723.2@4703.99,1689.05 v1(4727,1689) R723.2@4703.99,1689.05 ; C669.2@4703.99,1909.05 C669.2@4703.99,1909.05 v1(4732.5,1909) C669.2@4703.99,1909.05 ; C670.2@4703.99,1964.05 C670.2@4703.99,1964.05 v1(4728,1964) C670.2@4703.99,1964.05 ; C674.2@4742.99,1798.05 4744.94,1800 v1(4770,1800) C674.2@4742.99,1798.05 ; C683.2@4892.99,1444.05 4893.94,1445 v1(4918,1445) C683.2@4892.99,1444.05 ; C714.1@5173.05,1373.01 5173.5,1373.46 v1(5173.5,1396) C714.1@5173.05,1373.01 ; C649.2@5486,2491 5487,2490 5487,2483 v1(5505,2465) C649.2@5486,2491 ; C650.2@5529,2560.06 v1(5529,2584) C650.2@5528.99,2560.05 ; C727.1@6098,1378.06 C727.1@6098.05,1378.01 v1(6098,1402.5) C727.1@6098,1378.06 ; v1(6835,1381) 6835,1404 R12.2@6836,1405 v1(6835,1381)
  Top w20: J44.GND2@27.44,1451.2 v1(64,1416) ; J44.GND2@62.47,1466.73 v1(64,1416) ; J44.GND1@516.44,2556.87 v1(535,2515.3) ; J44.GND1@554.58,2556.41 v1(535,2515.3) ; C120.1@767,769.12 767.88,770 C120.1@767.88,773.5 ; C120.1@771.38,759.75 v1(767,716) 767,772.62 C120.1@767.88,773.5 ; C457.2@2268.41,2986 v1(2269,2955) 2269,2987.41 C457.2@2268.41,2988 2268,2988.41 v1(2268,3019) C457.2@2268.41,2990 ; C848.2@2352,2663 v1(2352,2687) ; C107.2@2356,2556 v1(2356,2586) ; CON54.2@2406.27,3024.8 v1(2410,2986) ; CON54.2@2406.31,3070.64 v1(2415,3106) ; CON54.2@2413.64,3059.49 v1(2380,3076) ; CON54.2@2414.44,3034.74 v1(2380,3021) ; CON54.2@2416.36,3013.71 v1(2380,3021) ; CON54.2@2417.23,3080.3 v1(2380,3076) ; CON54.2@2427.07,3021.05 v1(2410,2986) ; CON54.2@2427.39,3071.76 v1(2415,3106) ; v1(2511,2829) 2512,2828 C99.2@2512,2802 ; C100.2@2512,2902 v1(2512,2927) ; CON54.3@2522.61,3071.76 v1(2535,3106) ; v1(2528,2727) 2529,2726 L9.2@2529,2702 ; CON54.3@2533.91,3013.73 v1(2571,3022) ; CON54.3@2534.47,3080.21 v1(2571,3070) ; CON54.3@2534.67,3059.09 v1(2571,3070) ; CON54.3@2535.22,3034.81 v1(2571,3022) ; CON54.3@2543.63,3022.86 v1(2533,2986) ; CON54.3@2543.69,3070.64 v1(2535,3106) ; L6.2@2744.77,2719.23 2763.55,2738 v1(2764,2738) ; CON53.2@2751.37,2988.82 v1(2762,2953) ; CON53.2@2751.38,3037.22 v1(2762,3072) ; CON53.2@2755.99,3004.14 v1(2727,3030) ; CON53.2@2759.58,2979.95 v1(2726,2993) ; CON53.2@2761.13,3001 v1(2726,2993) ; CON53.2@2761.93,3035.64 v1(2762,3072) ; CON53.2@2765.24,3023.14 v1(2727,3030) ; CON53.2@2772.49,2988.86 v1(2762,2953) ; CON53.2@2772.49,3037.18 v1(2762,3072) ; C87.2@2784,2784 2784,2760 v1(2788,2760) ; C849.2@2854.27,2676.73 2872,2694.46 v1(2872,2695) ; v1(2858,2956) v1@2874.38,2956 ; CON53.3@2867.41,2989.85 v1@2874.38,2956 ; CON53.3@2867.64,2988.12 v1(2880,2956) ; CON53.3@2867.74,3038.32 v1(2882,3072) ; CON53.3@2878.07,3035.64 v1(2882,3072) ; CON53.3@2888.38,2987.6 v1@2874.38,2956 ; CON53.3@2888.69,2989.3 v1(2880,2956) ; CON53.3@2888.73,3036.05 v1(2882,3072) ; C456.2@2894.41,2732 2895,2731.41 v1(2895,2706) C456.2@2894.41,2733 ; U11.4@3194.14,3026.16 v1(3200,3065) ; U11.4@3204.77,3039.79 v1(3170,3025) ; U11.4@3205.83,3013.01 v1(3170,3025) ; U11.4@3211.69,3026.5 U11.4@3210.2,3025 ; U11.4@3220.44,3031.46 v1(3200,3065) ; C48.2@3268.45,2167 v1(3270,2135) 3270,2176.45 C48.2@3268.45,2178 ; U11.2@3289.56,2958.54 v1(3310,2925) ; U11.2@3298.31,2963.5 U11.2@3303.41,2958.41 ; U11.2@3305.92,2976.62 v1(3340,2960) ; U11.2@3315.86,2963.84 v1(3310,2925) ; C30.2@3326.59,2386 v1(3352,2367) 3331,2388 C30.2@3326.59,2388 ; J6.53@3653.09,4127.29 v1(3610,4175) ; J6.53@3665.84,4143.13 v1(3610,4175) ; J6.53@3671.78,4157.2 v1(3610,4175) ; J6.53@3671.87,4192.48 v1(3610,4175) ; J6.53@3674.23,4172.28 v1(3610,4175) ; J6.54@3680.84,3027.09 v1(3739,3066) ; J6.53@3689.5,4157.2 J6.53@3689.5,4160 ; J6.54@3694.44,3012.04 v1(3739,3066) ; J6.53@3703.68,4172.07 v1(3770,4180) ; J6.53@3704.36,4192.36 v1(3770,4180) ; J6.53@3704.93,4142.1 v1(3770,4140) ; C34.2@3709.45,2307 v1(3740,2300) 3715,2300 3715,2314.45 C34.2@3709.45,2320 ; C34.2@3709.45,2318 C34.2@3709.45,2320 ; C34.2@3709.45,2329 v1(3740,2335) 3715,2335 3709.45,2329.45 C34.2@3709.45,2320 ; C33.2@3710.45,2387 v1(3740,2380) 3710.45,2380 C33.2@3710.45,2398 3720,2407.55 3720,2410 v1(3740,2410) C33.2@3710.45,2409 ; J6.53@3712.95,4171.36 v1(3770,4140) ; J6.53@3714.03,4143.54 v1(3770,4180) ; J6.54@3721.5,2998.25 v1(3739,3066) ; J6.53@3725.4,4187.43 v1(3770,4140) ; J6.54@3741.66,2996.08 v1(3739,3066) ; C218.2@3804.55,2845 v1(3800,2810) C218.2@3800,2845 ; C218.2@3804.55,2856 3800,2851.45 C218.2@3800,2845 ; C218.2@3804.55,2867 v1(3802,2898) ; C193.2@4088.55,2971 v1(4085,2940) 4085,2986.45 C193.2@4087.55,2988 ; C193.2@4088.55,2993 v1@4087.55,3021 ; C217.2@4096,3590 v1(4120,3590) ; C216.2@4101,4030 v1(4127,4030) ; C119.1@4223.12,749.25 v1(4262.4,741.5) 4227.2,741.5 4227.2,762.92 C119.1@4223.12,767 ; C195.2@4417.45,2974 v1(4418,2940) 4418,2984.45 C195.2@4417.45,2985 ; C661.2@4545.44,1428.05 v1(4545,1397) 4545,1432.8 4545,1438.61 C661.2@4545.44,1439.05 ; C734.1@4882.88,660 4882.88,678.52 4874,687.4 v1(4849.3,687.4) C734.1@4882.88,675.75 ; C637.2@5359.54,1795.05 v1(5359,1765) 5359,1804.45 C637.2@5359.54,1804.99 ; U2.4@6717.61,3231 6717.61,3236.11 v1(6738,3256.5) U2.4@6729.72,3231 ; U3.4@6783,1778.5 v1(6785,1751) 6785,1788.61 U3.4@6783,1790.61 ; v1(64,1416) 64,1448.9 50.5,1462.4 J44.GND2@43.43,1462.4 v1(64,1416) ; v1(535,2515.3) 535,2560.27 J44.GND1@535.56,2560.83 v1(535,2515.3) ; v1(766.5,829.5) 767,821.9 v1@767.88,821.02 ; v1(766.5,829.5) C120.1@767.88,773.5 ; v1(766.5,829.5) 771.38,791.25 v1@767.88,821.02 ; C120.1@767.88,773.5 v1@767.88,821.02 ; v1(2380,3021) 2416.93,3021 CON54.2@2416.93,3031 ; v1(2380,3021) 2416.93,3024.36 v1(2410,2986) ; v1(2380,3076) 2416.93,3076 CON54.2@2416.93,3056 ; v1(2380,3076) 2416.93,3069.64 v1(2415,3106) ; v1(2410,2986) 2410,3044.07 CON54.2@2416.93,3051 ; v1(2415,3106) 2415,3032.93 CON54.2@2416.93,3031 ; CON54.2@2416.93,3031 CON54.2@2416.93,3051 ; CON54.2@2416.93,3031 CON54.2@2416.93,3047 ; CON54.2@2416.93,3047 CON54.2@2416.93,3051 ; CON54.2@2416.93,3047 CON54.2@2416.93,3056 ; CON54.2@2416.93,3051 CON54.2@2416.93,3056 ; v1(2533,2986) 2533,3048 CON54.3@2535,3050 ; v1(2533,2986) 2522.5,3022.9 v1(2533,2986) ; v1(2533,2986) 2533.07,3024.36 v1(2571,3022) ; CON54.3@2535,3050 2535,3028 2541,3022 v1(2571,3022) ; CON54.3@2535,3050 CON54.3@2535,3070 ; CON54.3@2535,3070 v1(2535,3106) ; CON54.3@2535,3070 v1(2571,3070) ; v1(2535,3106) 2533.07,3069.64 v1(2571,3070) ; v1(2726,2993) 2761.93,2993 CON53.2@2761.93,3010 ; v1(2726,2993) 2761.93,2990.36 v1(2762,2953) ; v1(2727,3030) CON53.2@2761.93,3030 ; v1(2727,3030) CON53.2@2761.93,3013 ; CON53.2@2761.93,3010 CON53.2@2761.93,3013 ; CON53.2@2761.93,3010 2762,3009.93 v1(2762,2953) ; CON53.2@2761.93,3013 CON53.2@2761.93,3030 ; CON53.2@2761.93,3030 2762,3030.07 v1(2762,3072) ; v1@2874.38,2956 v1@2878.07,2959.69 ; v1@2874.38,2956 CON53.3@2878.07,2990.36 ; v1@2878.07,2959.69 CON53.3@2878.07,3013 ; v1@2878.07,2959.69 2888.58,2988.51 v1@2878.07,2959.69 ; v1@2878.07,2959.69 2867.56,2988.51 v1@2878.07,2959.69 ; v1@2878.07,2959.69 CON53.3@2878.07,2990.36 ; v1@2878.07,2959.69 CON53.3@2878.07,2990.36 ; CON53.3@2878.07,2990.36 v1(2880,2956) ; CON53.3@2878.07,3013 CON53.3@2878.07,3023 ; CON53.3@2878.07,3013 v1(2880,2956) ; CON53.3@2878.07,3023 2877,3021.93 2877,3010 2880,3007 v1(2880,2956) ; CON53.3@2878.07,3023 2878.07,3032 2882,3032 v1(2882,3072) ; v1(3170,3025) U11.4@3210.2,3025 ; v1(3170,3025) 3207.76,3026.5 v1(3200,3065) ; v1(3200,3065) 3200,3035.2 U11.4@3210.2,3025 ; U11.2@3302.24,2963.5 v1(3310,2925) ; U11.2@3302.24,2963.5 v1(3340,2960) ; U11.2@3302.24,2963.5 v1(3340,2960) ; U11.2@3302.24,2963.5 v1(3310,2925) ; U11.2@3303.41,2958.41 3310,2951.81 v1(3310,2925) ; U11.2@3303.41,2958.41 3305,2960 v1(3340,2960) ; C30.2@3326.59,2388 3326.59,2389 v1(3353,2389) C30.2@3326.59,2388 ; v1(3340,2960) 3303.44,2949.93 v1(3340,2960) ; v1(3610,4175) J6.53@3690,4175 ; J6.53@3689.5,4160 3689.5,4174.5 J6.53@3690,4175 ; J6.53@3689.5,4160 3689.5,4140 v1(3770,4140) ; J6.53@3690,4175 3695,4180 v1(3770,4180) ; J6.54@3707.21,3003.66 v1@3737.03,2928 ; J6.54@3707.21,3003.66 v1(3739,3066) ; J6.54@3707.21,3003.66 v1(3746,2928) ; v1@3737.03,2928 J6.54@3737.03,3003.66 ; v1@3737.03,2928 v1(3746,2928) ; v1@3737.03,2928 3742.06,3009.17 v1(3746,2928) ; v1@3737.03,2928 3677.98,2983.92 v1(3746,2928) ; v1@3737.03,2928 3721.89,3007.9 v1(3746,2928) ; v1@3737.03,2928 3693.59,2996.75 v1(3746,2928) ; J6.54@3737.03,3003.66 J6.54@3689.5,3003.66 3739,3003.66 v1(3739,3066) ; J6.54@3737.03,3003.66 v1(3746,2928) ; v1(3770,4140) 3707.46,4121.93 v1(3770,4140) ; v1(3770,4140) 3707.21,4157.2 v1(3770,4180) ; v1(3770,4180) 3727.58,4128.4 v1(3770,4180) ; C218.2@3800,2845 C218.2@3802,2847 ; C218.2@3802,2847 v1(3802,2898) ; C218.2@3802,2847 v1(3802,2898) ; C193.2@4087.55,2983 v1(4055,2983) C193.2@4088.55,2982 C193.2@4087.55,2983 ; C193.2@4087.55,2983 C193.2@4087.55,2988 ; C193.2@4087.55,2988 v1@4087.55,3021 ; C193.2@4087.55,2988 v1(4087,3025) v1@4087.55,3021 ; C119.1@4223.12,767 4223.12,774.12 4229.4,780.4 v1(4262.8,780.4) C119.1@4223.12,765 C119.1@4223.12,767 ; C195.2@4417.45,2985 4419.45,2987 v1(4461,2987) C195.2@4417.45,2985 ; C55.2@3677,2262 3680,2262 v1(3703,2262) C55.2@3677,2262 ; C726.1@5948,1378.06 C726.1@5948.05,1378.01 v1(5948,1402) C726.1@5948,1378.06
